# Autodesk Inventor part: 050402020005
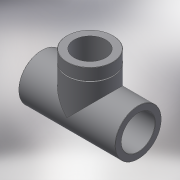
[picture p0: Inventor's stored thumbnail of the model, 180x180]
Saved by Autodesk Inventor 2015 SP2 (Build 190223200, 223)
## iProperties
Created: 2017-10
Part Number: 050402020005
Material: Generic
Description: PLASSON TEE THR-CEM REINF. P 20-1/2"
Document SubType Name: Modeling
Designer: KIM
Density: 1 g/cm^3
Appearance: Default
Author: KIM
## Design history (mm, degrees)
derived "057402.ipt"
feature "Solid1::057402.ipt"
feature "Solid2::057402.ipt"
tag "TaggingFeature1"
body "Solid1"
other parameters: "d0" = 55, "d1" = 27, "d2" = 16, "d5" = 16.7679, "d7" = 0.18631, "d8" = 16, "d9" = 28, "d10" = 27, "d15" = 0, "d18" = 18.631, "d24" = 0.18631, "d30" = 18.631, "d31" = 17, "d32" = 0, "d33" = 16.7679, "d35" = 0, "d37" = 0.5, "d38" = 0.5, "d39" = 7, "d40" = 27, "G_" = 18.631, "E_" = 27, "H_" = 55, "lt_" = 17, "l_" = 16, "h_" = 28
